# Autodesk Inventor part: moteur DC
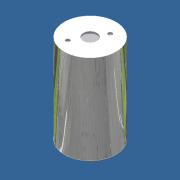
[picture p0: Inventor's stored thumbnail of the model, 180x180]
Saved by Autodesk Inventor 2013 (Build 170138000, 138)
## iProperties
Created: 2011-10
Part Number: moteur DC
Document SubType Name: Modeling
Designer: Laur
Density: 1 g/cm^3
Material: Générique
Author: Laur
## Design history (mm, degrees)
sketch "Esquisse1"
  geometry: C1 r 2.5 at (0, 0) reference
extrude "centrage" new body sketch "Esquisse1" distance "d0" = 0.8; taper "d1" = 0 deg
sketch "Esquisse2"
  geometry: C1 r 2.5 at (0, 0) reference; C2 r 6.25 at (0, 0)
  constraints: 1 centre point, 1 coincident
  dimensions: "d2" = 12.5 diameter of C2
extrude "stator" join sketch "Esquisse2" distance "d3" = 21.5; taper "d4" = 0 deg
sketch "Esquisse3"
  geometry: L1 (1.758, 3.076)-(-1.964, -3.436); C1 r 6.25 at (0, 0) reference; C2 r 1.65 at (0, 0); C3 r 0.5 at (1.758, 3.076); C4 r 0.5 at (-1.964, -3.436)
  constraints: 3 centre point, 3 coincident, 2 end point, 1 point on line
  dimensions: "d5" = 3.3 diameter of C2; "d8" = 7.5 distance of L1.start L1.end; "d9" = 1 diameter of C4; "d10" = 1 diameter of C3 (= d9)
extrude "fond moteur" cut sketch "Esquisse3" distance "d6" = 0.5; taper "d7" = 0 deg
sketch "Esquisse4"
  geometry: C1 r 2.5 at (0, 0) reference; C2 r 0.75 at (0, 0)
  constraints: 1 centre point, 1 coincident
  dimensions: "d11" = 1.5 diameter of C2
extrude "alésage arbre" cut sketch "Esquisse4" distance "d12" = 18; taper "d13" = 0 deg
sketch "Esquisse5"
  geometry: C1 r 0.8 at (-2.828, -2.828) reference; C2 r 0.8 at (2.828, 2.828) reference; 2 further points
  constraints: 2 coincident
hole "Perçage1" sketch "Esquisse5" at (2.828, 2.828), (-2.828, -2.828) diameter "d14" = 1.221; stored, may be unused: countersink angle "d18" = 90 deg, drill point angle "d20" = 118 deg; dims "d15" = 6, "d16" = 4, "d17" = 2, "d19" = 2
node "Solide1"
node "Corps solides"
node "Corps surfaciques"
node "Référence1"
node "Référence2"
node "Référence3"
